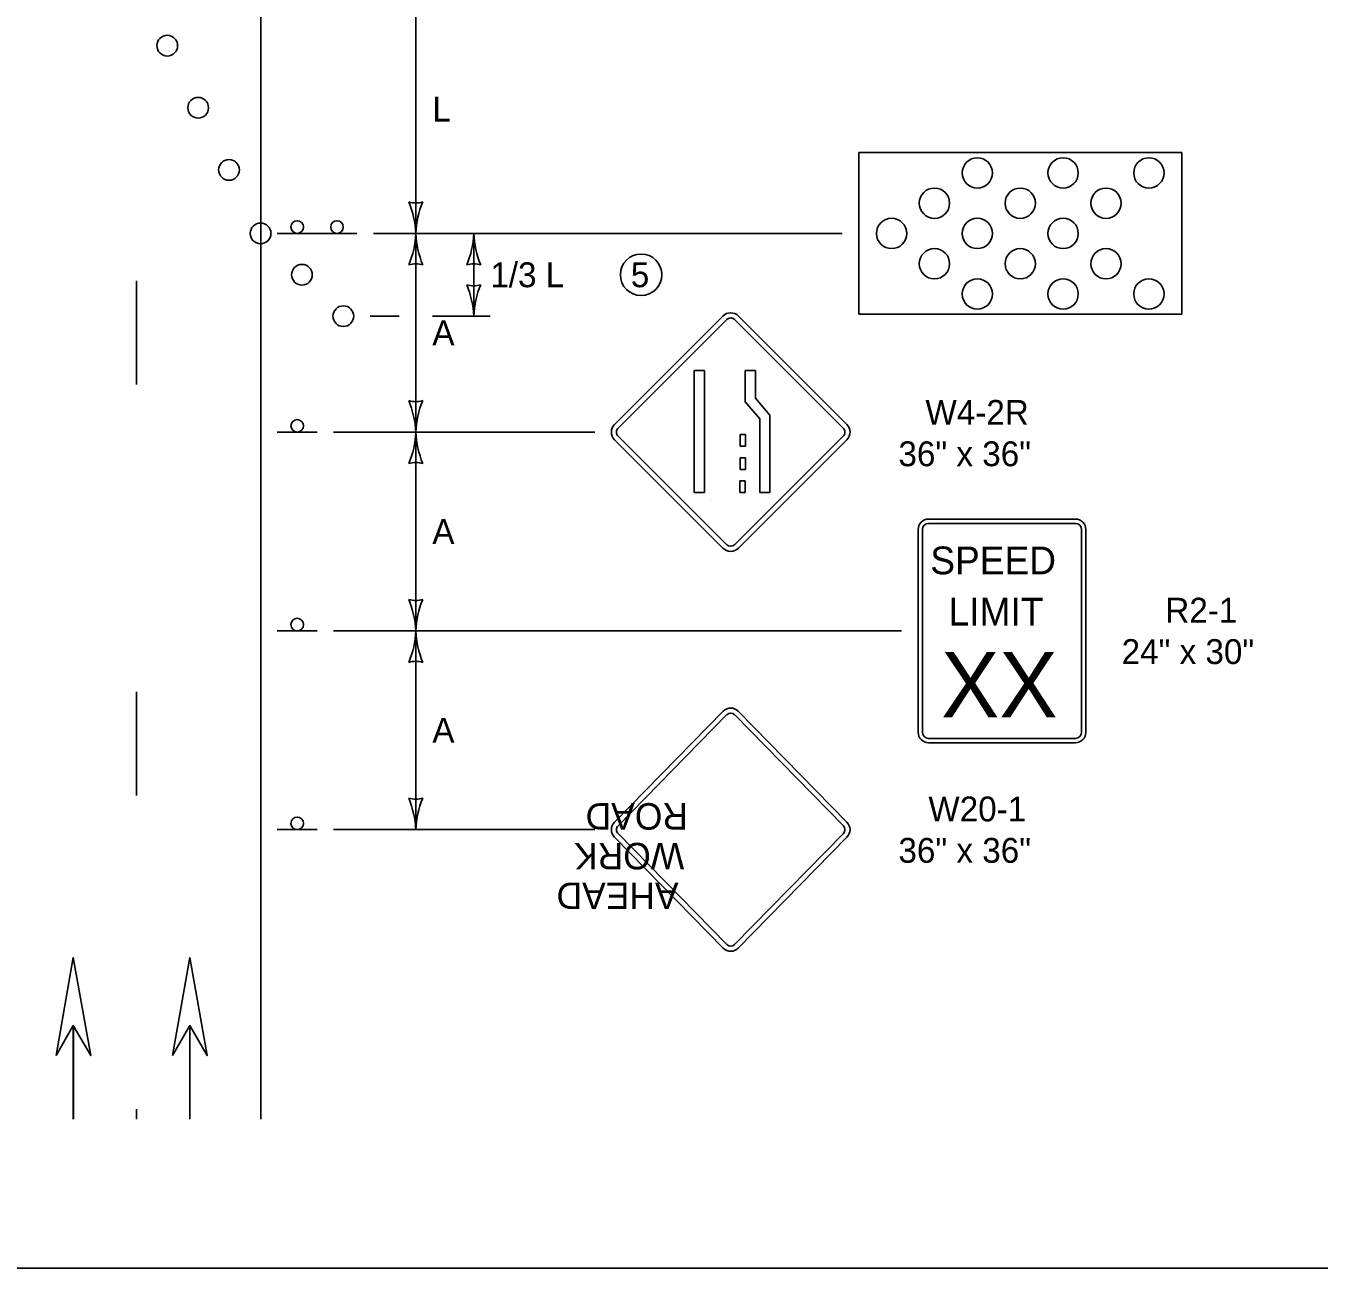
# Model space of a CAD drawing. Extents: x 49991.4 to 50021, y 49987.6 to 50011.4.
# Drawn here: x 50001.9 to 50005.023, y 49987.799 to 49990.799 of the extents above; entities that cross this region are included whole.
import ezdxf

# ---------------------------------------------------------------- set-up
doc = ezdxf.new("R2010")
doc.units = 0
for name, color, linetype in [('Level 1', 7, 'Continuous'), ('Level 2', 7, 'Continuous'), ('Level 25', 7, 'Continuous'), ('Level 3', 7, 'Continuous'), ('S_BOT_RW_TTL_Sheet_No_DF', 7, 'Continuous')]:
    doc.layers.add(name, color=color, linetype=linetype)

# ---------------------------------------------------------------- blocks, each defined once
blk = doc.blocks.new('ARR')
at = {"layer": 'Level 3'}
for centre, radius, start, end in [((1.53, 37.02), 37.05, 247.456, 267.6395), ((-21.37, 0), 9.13, 342.1388, 17.8612), ((1.92, -38.79), 38.83, 92.8273, 112.0772)]:
    blk.add_arc(centre, radius, start, end, dxfattribs=at)

msp = doc.modelspace()

# ---------------------------------------------------------------- linework, layer by layer
at = {"layer": 'Level 1'}
for p, q in [((50002.4673, 49988.1586), (50002.4673, 49992.9404)), ((50002.5073, 49990.2977), (50002.6033, 49990.2977)), ((50002.6033, 49990.2977), (50002.6993, 49990.2977)), ((50002.167, 49989.9331), (50002.167, 49990.1831)), ((50002.6033, 49989.8177), (50002.5073, 49989.8177)), ((50004.0545, 49989.093), (50004.0545, 49989.5824)), ((50004.0651, 49989.093), (50004.0651, 49989.5824)), ((50004.0799, 49989.6077), (50004.4343, 49989.6077)), ((50004.0799, 49989.5972), (50004.4343, 49989.5972)), ((50004.2571, 49989.6077), (50004.2571, 49989.6077)), ((50004.4491, 49989.5824), (50004.4491, 49989.093)), ((50004.4596, 49989.5824), (50004.4596, 49989.093)), ((50002.6033, 49989.3377), (50002.5073, 49989.3377)), ((50002.1674, 49988.9404), (50002.1674, 49989.1904)), ((50003.3212, 49988.8757), (50003.584, 49989.144)), ((50003.62, 49989.144), (50003.8828, 49988.8757)), ((50003.33, 49988.8671), (50003.5928, 49989.1354)), ((50003.6112, 49989.1354), (50003.874, 49988.8671)), ((50004.4343, 49989.0782), (50004.0799, 49989.0782)), ((50004.4343, 49989.0677), (50004.0799, 49989.0677)), ((50002.6033, 49988.8577), (50002.5073, 49988.8577)), ((50003.584, 49988.5716), (50003.3212, 49988.8398)), ((50003.5928, 49988.5802), (50003.33, 49988.8484)), ((50003.874, 49988.8484), (50003.6112, 49988.5802)), ((50003.8828, 49988.8398), (50003.62, 49988.5716)), ((50002.0147, 49988.1586), (50002.0147, 49988.3845)), ((50002.0151, 49988.1586), (50002.0151, 49988.3845)), ((50002.2957, 49988.1586), (50002.2957, 49988.3845)), ((50002.2961, 49988.1586), (50002.2961, 49988.3845)), ((50002.167, 49988.1586), (50002.167, 49988.1831))]:
    msp.add_line(p, q, dxfattribs=at)
for points in [[(49999.3835, 49998.9992), (50016.7501, 49998.9992), (50016.7501, 49987.7988), (49999.3835, 49987.7988)], [(50003.9115, 49990.1027), (50004.6912, 49990.1027), (50004.6912, 49990.4927), (50003.9115, 49990.4927)], [(50003.9115, 49990.1027), (50004.6912, 49990.1027), (50004.6912, 49990.4927), (50003.9115, 49990.4927)], [(50001.9731, 49988.3122), (50002.0147, 49988.5487), (50002.0567, 49988.3122), (50002.0147, 49988.3844)], [(50002.2541, 49988.3122), (50002.2957, 49988.5487), (50002.3377, 49988.3122), (50002.2957, 49988.3844)]]:
    msp.add_lwpolyline(points, close=True, dxfattribs=at)
for centre, radius in [((50002.2415, 49990.751), 0.025), ((50002.3161, 49990.601), 0.025), ((50002.3906, 49990.451), 0.025), ((50004.1976, 49990.4437), 0.0366), ((50004.1976, 49990.4437), 0.0366), ((50004.4047, 49990.4437), 0.0366), ((50004.4047, 49990.4437), 0.0366), ((50004.6118, 49990.4437), 0.0366), ((50004.6118, 49990.4437), 0.0366), ((50004.094, 49990.3706), 0.0366), ((50004.094, 49990.3706), 0.0366), ((50004.3012, 49990.3706), 0.0366), ((50004.3012, 49990.3706), 0.0366), ((50004.5083, 49990.3706), 0.0366), ((50004.5083, 49990.3706), 0.0366), ((50002.5553, 49990.3129), 0.0152), ((50002.6513, 49990.3129), 0.0152), ((50003.9905, 49990.2975), 0.0366), ((50003.9905, 49990.2975), 0.0366), ((50004.1976, 49990.2975), 0.0366), ((50004.1976, 49990.2975), 0.0366), ((50004.4047, 49990.2975), 0.0366), ((50004.4047, 49990.2975), 0.0366), ((50002.4668, 49990.2977), 0.025), ((50004.094, 49990.2244), 0.0366), ((50004.094, 49990.2244), 0.0366), ((50004.3012, 49990.2244), 0.0366), ((50004.3012, 49990.2244), 0.0366), ((50004.5083, 49990.2244), 0.0366), ((50004.5083, 49990.2244), 0.0366), ((50002.5668, 49990.1977), 0.025), ((50004.1976, 49990.1513), 0.0366), ((50004.1976, 49990.1513), 0.0366), ((50004.4047, 49990.1513), 0.0366), ((50004.4047, 49990.1513), 0.0366), ((50004.6118, 49990.1513), 0.0366), ((50004.6118, 49990.1513), 0.0366), ((50002.6667, 49990.0977), 0.025), ((50002.5553, 49989.8329), 0.0152), ((50002.5553, 49989.3529), 0.0152), ((50002.5553, 49988.8729), 0.0152)]:
    msp.add_circle(centre, radius, dxfattribs=at)
for centre, radius, start, end in [((50002.2415, 49990.751), 0.025, 0, 180), ((50002.2415, 49990.751), 0.025, 180, 0), ((50002.3161, 49990.601), 0.025, 0, 180), ((50002.3161, 49990.601), 0.025, 180, 0), ((50002.3906, 49990.451), 0.025, 0, 180), ((50002.3906, 49990.451), 0.025, 180, 0), ((50002.4668, 49990.2977), 0.025, 0, 180), ((50002.4668, 49990.2977), 0.025, 180, 0), ((50002.5668, 49990.1977), 0.025, 0, 180), ((50002.5668, 49990.1977), 0.025, 180, 0), ((50002.6667, 49990.0977), 0.025, 0, 180), ((50002.6667, 49990.0977), 0.025, 180, 0), ((50004.0799, 49989.5824), 0.0253, 90, 180), ((50004.0799, 49989.5824), 0.0148, 90, 180), ((50004.4343, 49989.5824), 0.0253, 0, 90), ((50004.4343, 49989.5824), 0.0148, 0, 90), ((50004.0799, 49989.093), 0.0253, 180, 270), ((50004.0799, 49989.093), 0.0148, 180, 270), ((50004.4343, 49989.093), 0.0148, 270, 360), ((50004.4343, 49989.093), 0.0253, 270, 360)]:
    msp.add_arc(centre, radius, start, end, dxfattribs=at)
for centre, major_axis, ratio, start_param, end_param in [((50003.602, 49989.1259), (0, 0.0255), 0.98963, 5.497787, 7.068583), ((50003.602, 49989.1259), (0, 0.0132), 0.98, 5.497787, 7.068583), ((50003.3392, 49988.8577), (0, 0.0255), 0.98963, 0.785394, 2.356194), ((50003.3392, 49988.8577), (0, 0.0132), 0.98, 0.785394, 2.356194), ((50003.8649, 49988.8577), (0, 0.0132), 0.98, 3.926991, 5.497787), ((50003.8649, 49988.8577), (0, 0.0255), 0.98963, 3.926991, 5.497787), ((50003.602, 49988.5895), (0, -0.0132), 0.98, 5.497795, 7.068583), ((50003.602, 49988.5895), (0, -0.0255), 0.98963, 5.497795, 7.068583)]:
    msp.add_ellipse(centre, major_axis=major_axis, ratio=ratio, start_param=start_param, end_param=end_param, dxfattribs=at)
at = {"layer": 'Level 2'}
msp.add_circle((50003.3857, 49990.1977), 0.0501, dxfattribs=at)
at = {"layer": 'Level 25'}
for p, q in [((50003.3216, 49989.8364), (50003.5833, 49990.0981)), ((50003.5921, 49990.0892), (50003.3305, 49989.8276)), ((50003.5921, 49990.0892), (50003.5921, 49990.0892)), ((50003.8735, 49989.8276), (50003.6119, 49990.0892)), ((50003.6207, 49990.0981), (50003.8824, 49989.8364)), ((50003.5387, 49989.9668), (50003.5142, 49989.9668)), ((50003.5142, 49989.9668), (50003.5142, 49989.6717)), ((50003.5387, 49989.6717), (50003.5387, 49989.9668)), ((50003.5833, 49989.5373), (50003.3216, 49989.799)), ((50003.3305, 49989.8078), (50003.5921, 49989.5462)), ((50003.6119, 49989.5462), (50003.8735, 49989.8078)), ((50003.8824, 49989.799), (50003.6207, 49989.5373)), ((50003.5142, 49989.6717), (50003.5387, 49989.6717))]:
    msp.add_line(p, q, dxfattribs=at)
msp.add_lwpolyline([(50003.5548, 49989.6532), (50003.555, 49989.6534)], dxfattribs=at)
for centre, radius, start, end in [((50003.602, 49990.0794), 0.0264, 45.0001, 134.9999), ((50003.602, 49990.0794), 0.014, 45.0001, 134.9999), ((50003.3403, 49989.8177), 0.0264, 134.9999, 225.0001), ((50003.8637, 49989.8177), 0.0264, 314.9999, 45.0001), ((50003.3403, 49989.8177), 0.014, 134.9999, 225.0001), ((50003.8637, 49989.8177), 0.014, 314.9999, 45.0001), ((50003.602, 49989.556), 0.0264, 225.0001, 314.9999), ((50003.602, 49989.556), 0.014, 225.0001, 314.9999)]:
    msp.add_arc(centre, radius, start, end, dxfattribs=at)
at = {"layer": 'Level 3'}
for p, q in [((50002.8416, 49990.2977), (50002.8416, 49990.8977)), ((50002.7393, 49990.2977), (50002.9816, 49990.2977)), ((50002.8416, 49989.8177), (50002.8416, 49990.2977)), ((50002.9816, 49990.2977), (50002.9816, 49990.0977)), ((50002.9816, 49990.2977), (50003.8715, 49990.2977)), ((50002.7317, 49990.0977), (50002.8016, 49990.0977)), ((50002.8816, 49990.0977), (50003.0216, 49990.0977)), ((50003.2739, 49989.8177), (50002.6433, 49989.8177)), ((50002.8416, 49989.3377), (50002.8416, 49989.8177)), ((50004.0145, 49989.3377), (50002.6433, 49989.3377)), ((50002.8416, 49989.3377), (50002.8416, 49988.8577)), ((50003.2739, 49988.8577), (50002.6433, 49988.8577))]:
    msp.add_line(p, q, dxfattribs=at)
for centre, radius, start, end in [((50002.8416, 49990.4259), 0.0548, 252.1388, 287.8612), ((50002.6089, 49990.2862), 0.233, 2.8273, 22.0772), ((50003.0637, 49990.2885), 0.2223, 157.456, 177.6395), ((50002.7594, 49990.3069), 0.2223, 337.456, 357.6395), ((50003.2143, 49990.3092), 0.233, 182.8273, 202.0772), ((50002.9816, 49990.1695), 0.0548, 72.1388, 107.8612), ((50002.9816, 49990.2259), 0.0548, 252.1388, 287.8612), ((50002.7489, 49990.0862), 0.233, 2.8273, 22.0772), ((50003.2037, 49990.0885), 0.2223, 157.456, 177.6395)]:
    msp.add_arc(centre, radius, start, end, dxfattribs=at)
at = {"layer": 'S_BOT_RW_TTL_Sheet_No_DF'}
for p, q in [((50003.6373, 49989.8905), (50003.6373, 49989.9668)), ((50003.6373, 49989.9668), (50003.6618, 49989.9668)), ((50003.6618, 49989.9668), (50003.6618, 49989.8995)), ((50003.6618, 49989.8995), (50003.6968, 49989.8589)), ((50003.6723, 49989.8498), (50003.6373, 49989.8905)), ((50003.6723, 49989.6717), (50003.6723, 49989.8498)), ((50003.6968, 49989.8589), (50003.6968, 49989.6717)), ((50003.6245, 49989.7837), (50003.6245, 49989.8117)), ((50003.6245, 49989.8117), (50003.6375, 49989.8117)), ((50003.6375, 49989.8117), (50003.6375, 49989.7837)), ((50003.6375, 49989.7837), (50003.6245, 49989.7837)), ((50003.6245, 49989.7277), (50003.6245, 49989.7557)), ((50003.6245, 49989.7557), (50003.6375, 49989.7557)), ((50003.6375, 49989.7557), (50003.6375, 49989.7277)), ((50003.6375, 49989.7277), (50003.6245, 49989.7277)), ((50003.6242, 49989.6717), (50003.6242, 49989.6997)), ((50003.6242, 49989.6997), (50003.6372, 49989.6997)), ((50003.6372, 49989.6997), (50003.6372, 49989.6717)), ((50003.6372, 49989.6717), (50003.6242, 49989.6717)), ((50003.6968, 49989.6717), (50003.6723, 49989.6717))]:
    msp.add_line(p, q, dxfattribs=at)

# ---------------------------------------------------------------- block references
at = {"layer": 'Level 2', "xscale": 0.006, "yscale": 0.006}
for p, rotation in [((50002.8416, 49990.2977), 90), ((50002.8416, 49989.8177), -90), ((50002.8416, 49989.8177), 90), ((50002.8416, 49989.3377), -90), ((50002.8416, 49989.3377), 90), ((50002.8416, 49988.8577), -90)]:
    msp.add_blockref('ARR', p, dxfattribs=dict(at, rotation=rotation))

# ---------------------------------------------------------------- texts
at = {"layer": 'Level 1'}
for s, height, p in [('SPEED', 0.06695, (50004.084, 49989.4745)), ('LIMIT', 0.06695, (50004.1283, 49989.3507)), ('XX', 0.15772, (50004.11, 49989.1288))]:
    msp.add_text(s, height=height, dxfattribs=at).set_placement(p)
for s, p in [('ROAD', (50003.4988, 49988.9217)), ('WORK', (50003.4898, 49988.8258)), ('AHEAD', (50003.4762, 49988.7299))]:
    msp.add_text(s, height=0.06395, rotation=180, dxfattribs=at).set_placement(p)
at = {"layer": 'Level 2'}
for s, p in [('L', (50002.8816, 49990.5677)), ('1/3 L', (50003.0216, 49990.1677)), ('5', (50003.3608, 49990.1677)), ('A', (50002.8816, 49990.0277)), ('W4-2R', (50004.0722, 49989.8354)), ('36" x 36"', (50004.007, 49989.7354)), ('A', (50002.8816, 49989.5477)), ('R2-1', (50004.6515, 49989.3577)), ('24" x 30"', (50004.5459, 49989.2577)), ('A', (50002.8816, 49989.0677)), ('W20-1', (50004.0793, 49988.8777)), ('36" x 36"', (50004.007, 49988.7777))]:
    msp.add_text(s, height=0.06, dxfattribs=at).set_placement(p)

doc.saveas('drawing.dxf')
